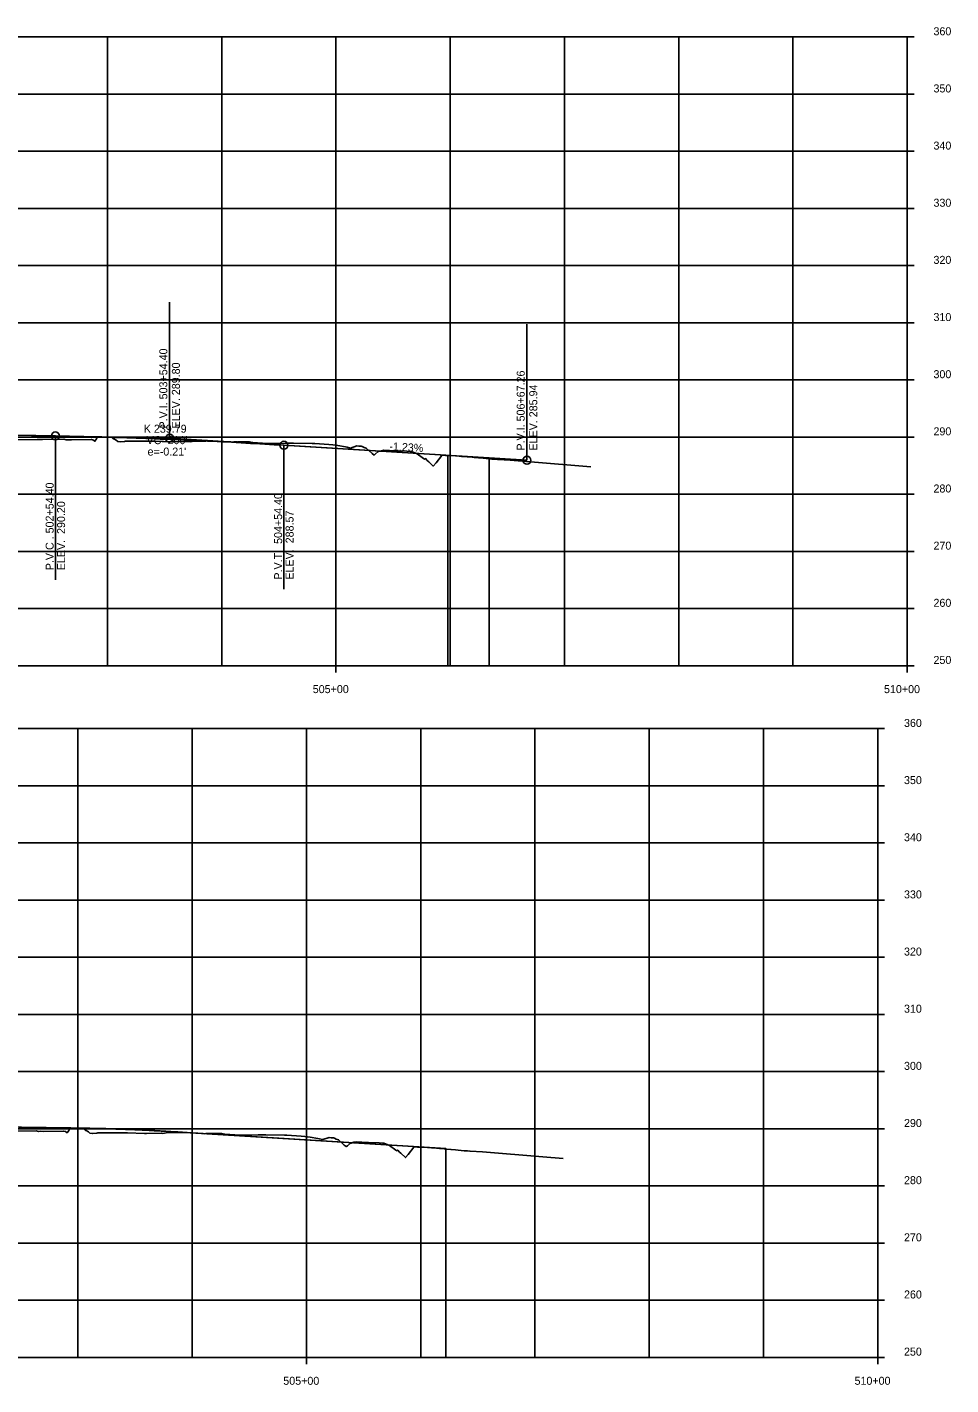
# Model space of a CAD drawing. Extents: x 1300404 to 1323571, y 234004 to 252077.
# Drawn here: x 1319459 to 1320268, y 238049 to 239237 of the extents above; entities that cross this region are included whole.
import ezdxf

# ---------------------------------------------------------------- set-up
doc = ezdxf.new("R2010")
doc.units = 0
for name, color, linetype in [('R_Axis', 7, 'Continuous'), ('R_Axis Annot', 7, 'Continuous'), ('R_Exist Surface', 7, 'Continuous'), ('R_Grid', 7, 'Continuous'), ('R_Temp Barrier Wall', 7, 'Continuous'), ('R_Vert Alg', 7, 'Continuous'), ('R_Vert Alg Annot', 7, 'Continuous')]:
    doc.layers.add(name, color=color, linetype=linetype)

msp = doc.modelspace()

# ---------------------------------------------------------------- linework, layer by layer
at = {"layer": 'R_Axis'}
for p, q in [((1320229.6, 238678), (1320229.6, 239228)), ((1320235.6, 239228), (1320229.6, 239228)), ((1320235.6, 239228), (1320229.6, 239228)), ((1320235.6, 239178), (1320229.6, 239178)), ((1320235.6, 239128), (1320229.6, 239128)), ((1320235.6, 239078), (1320229.6, 239078)), ((1320235.6, 239028), (1320229.6, 239028)), ((1320235.6, 238978), (1320229.6, 238978)), ((1320235.6, 238928), (1320229.6, 238928)), ((1320235.6, 238878), (1320229.6, 238878)), ((1320235.6, 238828), (1320229.6, 238828)), ((1320235.6, 238778), (1320229.6, 238778)), ((1320235.6, 238728), (1320229.6, 238728)), ((1318729.6, 238678), (1320229.6, 238678)), ((1319729.6, 238672), (1319729.6, 238678)), ((1320235.6, 238678), (1320229.6, 238678)), ((1320229.6, 238672), (1320229.6, 238678)), ((1320203.8, 238072.9), (1320203.8, 238622.9)), ((1320209.8, 238622.9), (1320203.8, 238622.9)), ((1320209.8, 238622.9), (1320203.8, 238622.9)), ((1320209.8, 238572.9), (1320203.8, 238572.9)), ((1320209.8, 238522.9), (1320203.8, 238522.9)), ((1320209.8, 238472.9), (1320203.8, 238472.9)), ((1320209.8, 238422.9), (1320203.8, 238422.9)), ((1320209.8, 238372.9), (1320203.8, 238372.9)), ((1320209.8, 238322.9), (1320203.8, 238322.9)), ((1320209.8, 238272.9), (1320203.8, 238272.9)), ((1320209.8, 238222.9), (1320203.8, 238222.9)), ((1320209.8, 238172.9), (1320203.8, 238172.9)), ((1320209.8, 238122.9), (1320203.8, 238122.9)), ((1318703.8, 238072.9), (1320203.8, 238072.9)), ((1319703.8, 238066.9), (1319703.8, 238072.9)), ((1320209.8, 238072.9), (1320203.8, 238072.9)), ((1320203.8, 238066.9), (1320203.8, 238072.9))]:
    msp.add_line(p, q, dxfattribs=at)
at = {"layer": 'R_Exist Surface'}
for points in [[(1319448.9, 238875.7), (1319468.1, 238875.9), (1319470.3, 238875.9), (1319472.8, 238875.9), (1319491.4, 238876.1), (1319493.6, 238875.7), (1319495.6, 238875.7), (1319498.1, 238875.5), (1319515.3, 238875.8), (1319515.4, 238875.8), (1319515.6, 238875.9), (1319517.3, 238875.4), (1319518.6, 238874.4), (1319519.9, 238876.5), (1319521, 238878.2), (1319524.7, 238878.3), (1319533.5, 238877.5), (1319534.6, 238876.4), (1319534.8, 238876.5), (1319535.2, 238876.4), (1319537.3, 238875.3), (1319538.6, 238874), (1319540.8, 238873.7), (1319544.5, 238874.2), (1319545.3, 238874.3), (1319557, 238874.3), (1319557.3, 238874.4), (1319569.1, 238874.4), (1319571.3, 238874.3), (1319586.2, 238873.8), (1319587.1, 238873.8), (1319587.7, 238873.9), (1319588.2, 238873.9), (1319600.9, 238874.2), (1319602.5, 238873.9), (1319605.2, 238874.3), (1319615.7, 238874.5), (1319620.9, 238874.7), (1319636.6, 238873.8), (1319637.5, 238873.7), (1319638.7, 238873.5), (1319640.1, 238873.7), (1319642.9, 238873.7), (1319643.2, 238873.7), (1319643.3, 238873.6), (1319643.4, 238873.6), (1319644, 238873.7), (1319653.9, 238873.8), (1319656.5, 238873.1), (1319656.7, 238873.1), (1319665.4, 238872.6), (1319667.7, 238872.5), (1319685.8, 238872.8), (1319686.4, 238872.8), (1319692.4, 238872.7), (1319708.9, 238872.4), (1319709.4, 238872.4), (1319711, 238872.3), (1319723.4, 238871.4), (1319726.8, 238871.1), (1319729, 238871), (1319731.3, 238870.6), (1319738, 238869.4), (1319739.3, 238869.2), (1319742.4, 238868.4), (1319748, 238870.2), (1319749.7, 238870.1), (1319751.7, 238870.1), (1319752.6, 238869.7), (1319754.2, 238869), (1319756.1, 238868.4), (1319761.2, 238863.7), (1319762.9, 238862.3), (1319764, 238863), (1319766.6, 238865.3), (1319767.1, 238865.4), (1319769.5, 238866.1), (1319771.6, 238866.4), (1319771.6, 238866.4), (1319771.6, 238866.4), (1319781.7, 238866), (1319782.5, 238866), (1319791.6, 238865.7), (1319794.7, 238865.4), (1319795.7, 238865.3), (1319796.3, 238865.1), (1319797.3, 238864.7), (1319800.8, 238863.2), (1319806.3, 238859.2), (1319807, 238858.8), (1319808, 238859.2), (1319809.4, 238857.6), (1319810.8, 238856.4), (1319814.8, 238852.6), (1319817.2, 238855.5), (1319822.2, 238861.9), (1319822.3, 238862), (1319822.4, 238862.1), (1319822.5, 238862.1), (1319825.4, 238862), (1319827.8, 238862), (1319834.1, 238861.6), (1319834.7, 238861.5), (1319837.4, 238861.4), (1319839, 238861.2), (1319839.9, 238861.1), (1319840, 238861.1), (1319841.9, 238860.9), (1319843, 238860.9), (1319844.5, 238860.7), (1319845.5, 238860.6), (1319848.7, 238860.3), (1319850.5, 238860.1), (1319850.7, 238860.1), (1319851, 238860), (1319854.5, 238859.7), (1319854.5, 238859.7), (1319854.7, 238859.7), (1319858.4, 238859.4), (1319858.4, 238859.4), (1319858.5, 238859.4), (1319861, 238859.2), (1319861, 238859.2), (1319866, 238858.8), (1319866, 238858.8), (1319866, 238858.8), (1319869.1, 238858.6), (1319871, 238858.5), (1319871.4, 238858.5), (1319882.1, 238857.7), (1319899.8, 238856.3), (1319917.4, 238854.8), (1319935.1, 238853.4), (1319952.7, 238851.9)], [(1319448.5, 238270.8), (1319467.1, 238271), (1319469.3, 238270.6), (1319471.4, 238270.7), (1319473.8, 238270.5), (1319491, 238270.8), (1319491.1, 238270.8), (1319491.3, 238270.9), (1319493, 238270.4), (1319494.3, 238269.4), (1319495.7, 238271.4), (1319496.7, 238273.1), (1319500.4, 238273.2), (1319509.2, 238272.4), (1319510.3, 238271.4), (1319510.5, 238271.4), (1319510.9, 238271.4), (1319513, 238270.2), (1319514.3, 238269), (1319516.5, 238268.6), (1319520.2, 238269.1), (1319521.1, 238269.3), (1319532.7, 238269.3), (1319533.1, 238269.3), (1319544.9, 238269.3), (1319547, 238269.3), (1319561.9, 238268.7), (1319562.8, 238268.8), (1319563.4, 238268.8), (1319563.9, 238268.8), (1319576.7, 238269.1), (1319578.2, 238268.8), (1319580.9, 238269.2), (1319591.4, 238269.5), (1319596.6, 238269.6), (1319612.3, 238268.8), (1319613.2, 238268.6), (1319614.5, 238268.5), (1319615.8, 238268.6), (1319618.6, 238268.6), (1319619, 238268.6), (1319619, 238268.5), (1319619.1, 238268.6), (1319619.7, 238268.6), (1319629.6, 238268.7), (1319632.2, 238268.1), (1319632.4, 238268), (1319641.1, 238267.5), (1319643.4, 238267.4), (1319661.5, 238267.7), (1319662.1, 238267.7), (1319668.2, 238267.7), (1319684.6, 238267.3), (1319685.1, 238267.3), (1319686.7, 238267.3), (1319699.1, 238266.3), (1319702.5, 238266), (1319704.7, 238265.9), (1319707, 238265.6), (1319713.7, 238264.3), (1319715, 238264.1), (1319718.1, 238263.4), (1319723.7, 238265.1), (1319725.4, 238265), (1319727.4, 238265), (1319728.3, 238264.6), (1319729.9, 238263.9), (1319731.9, 238263.3), (1319736.9, 238258.6), (1319738.6, 238257.3), (1319739.7, 238257.9), (1319742.4, 238260.2), (1319742.8, 238260.4), (1319745.2, 238261), (1319747.3, 238261.4), (1319747.3, 238261.4), (1319747.3, 238261.4), (1319757.4, 238260.9), (1319758.2, 238260.9), (1319767.3, 238260.6), (1319770.4, 238260.3), (1319771.4, 238260.2), (1319772, 238260), (1319773, 238259.6), (1319776.5, 238258.1), (1319782, 238254.2), (1319782.7, 238253.7), (1319783.7, 238254.2), (1319785.1, 238252.5), (1319786.5, 238251.4), (1319790.5, 238247.6), (1319792.9, 238250.4), (1319797.9, 238256.8), (1319798, 238256.9), (1319798.1, 238257), (1319798.2, 238257), (1319801.1, 238256.9), (1319803.5, 238256.9), (1319809.8, 238256.5), (1319810.4, 238256.5), (1319813.1, 238256.3), (1319814.7, 238256.2), (1319815.6, 238256.1), (1319815.7, 238256.1), (1319817.6, 238255.9), (1319818.7, 238255.8), (1319820.2, 238255.6), (1319821.2, 238255.5), (1319824.4, 238255.2), (1319826.2, 238255), (1319826.4, 238255), (1319826.7, 238255), (1319830.2, 238254.6), (1319830.2, 238254.6), (1319830.4, 238254.6), (1319834.1, 238254.3), (1319834.2, 238254.3), (1319834.2, 238254.3), (1319836.7, 238254.1), (1319836.7, 238254.1), (1319841.7, 238253.7), (1319841.7, 238253.7), (1319841.7, 238253.7), (1319844.8, 238253.5), (1319846.7, 238253.4), (1319847.1, 238253.4), (1319857.8, 238252.7), (1319875.5, 238251.2), (1319893.1, 238249.8), (1319910.8, 238248.3), (1319928.4, 238246.8)]]:
    msp.add_lwpolyline(points, dxfattribs=at)
at = {"layer": 'R_Grid'}
for p, q in [((1318729.6, 239228), (1320229.6, 239228)), ((1318729.6, 239228), (1320229.6, 239228)), ((1319529.6, 238678), (1319529.6, 239228)), ((1319629.6, 238678), (1319629.6, 239228)), ((1319729.6, 238678), (1319729.6, 239228)), ((1319829.6, 238678), (1319829.6, 239228)), ((1319929.6, 238678), (1319929.6, 239228)), ((1320029.6, 238678), (1320029.6, 239228)), ((1320129.6, 238678), (1320129.6, 239228)), ((1318729.6, 239178), (1320229.6, 239178)), ((1318729.6, 239128), (1320229.6, 239128)), ((1318729.6, 239078), (1320229.6, 239078)), ((1318729.6, 239028), (1320229.6, 239028)), ((1318729.6, 238978), (1320229.6, 238978)), ((1318729.6, 238928), (1320229.6, 238928)), ((1318729.6, 238878), (1320229.6, 238878)), ((1318729.6, 238828), (1320229.6, 238828)), ((1318729.6, 238778), (1320229.6, 238778)), ((1318729.6, 238728), (1320229.6, 238728)), ((1318703.8, 238622.9), (1320203.8, 238622.9)), ((1318703.8, 238622.9), (1320203.8, 238622.9)), ((1319503.8, 238072.9), (1319503.8, 238622.9)), ((1319603.8, 238072.9), (1319603.8, 238622.9)), ((1319703.8, 238072.9), (1319703.8, 238622.9)), ((1319803.8, 238072.9), (1319803.8, 238622.9)), ((1319903.8, 238072.9), (1319903.8, 238622.9)), ((1320003.8, 238072.9), (1320003.8, 238622.9)), ((1320103.8, 238072.9), (1320103.8, 238622.9)), ((1318703.8, 238572.9), (1320203.8, 238572.9)), ((1318703.8, 238522.9), (1320203.8, 238522.9)), ((1318703.8, 238472.9), (1320203.8, 238472.9)), ((1318703.8, 238422.9), (1320203.8, 238422.9)), ((1318703.8, 238372.9), (1320203.8, 238372.9)), ((1318703.8, 238322.9), (1320203.8, 238322.9)), ((1318703.8, 238272.9), (1320203.8, 238272.9)), ((1318703.8, 238222.9), (1320203.8, 238222.9)), ((1318703.8, 238172.9), (1320203.8, 238172.9)), ((1318703.8, 238122.9), (1320203.8, 238122.9))]:
    msp.add_line(p, q, dxfattribs=at)
at = {"layer": 'R_Temp Barrier Wall'}
for p, q in [((1319584, 238877), (1319213.5, 238884.4)), ((1319896.8, 238857.7), (1319584, 238877)), ((1319827.6, 238678), (1319827.6, 238862)), ((1319863.6, 238678), (1319863.6, 238859)), ((1319203.4, 238278), (1319547.5, 238272.8)), ((1319547.5, 238272.8), (1319825.8, 238255.5)), ((1319803.8, 238072.9), (1319803.8, 238256.9)), ((1319825.8, 238072.9), (1319825.8, 238255.5))]:
    msp.add_line(p, q, dxfattribs=at)
at = {"layer": 'R_Vert Alg'}
for p, q in [((1319584, 238877), (1319584, 238996)), ((1319896.8, 238857.7), (1319896.8, 238976.7)), ((1319263.5, 238883.4), (1319484, 238879)), ((1319484, 238879), (1319484, 238753)), ((1319534, 238878), (1319584, 238877)), ((1319584, 238877), (1319634, 238873.9)), ((1319684, 238870.8), (1319684, 238744.8)), ((1319684, 238870.8), (1319896.8, 238857.7)), ((1319258.4, 238277.2), (1319497.5, 238273.6)), ((1319597.5, 238269.7), (1319825.8, 238255.5))]:
    msp.add_line(p, q, dxfattribs=at)
for points in [[(1319484, 238879), (1319488.1, 238878.9), (1319492.3, 238878.8), (1319496.5, 238878.7), (1319500.6, 238878.6), (1319504.8, 238878.5), (1319509, 238878.4), (1319513.1, 238878.3), (1319517.3, 238878.2), (1319521.5, 238878.1), (1319525.6, 238878), (1319529.8, 238877.9), (1319534, 238877.7), (1319538.1, 238877.6), (1319542.3, 238877.5), (1319546.5, 238877.3), (1319550.6, 238877.2), (1319554.8, 238877.1), (1319559, 238876.9), (1319563.1, 238876.8), (1319567.3, 238876.6), (1319571.5, 238876.5), (1319575.6, 238876.3), (1319579.8, 238876.1), (1319588.1, 238875.8), (1319592.3, 238875.6), (1319596.5, 238875.4), (1319600.6, 238875.3), (1319604.8, 238875.1), (1319609, 238874.9), (1319613.1, 238874.7), (1319617.3, 238874.5), (1319621.5, 238874.3), (1319625.6, 238874.1), (1319629.8, 238873.9), (1319634, 238873.7), (1319638.1, 238873.4), (1319642.3, 238873.2), (1319646.5, 238873), (1319650.6, 238872.8), (1319654.8, 238872.5), (1319659, 238872.3), (1319663.1, 238872.1), (1319667.3, 238871.8), (1319671.5, 238871.6), (1319675.6, 238871.3), (1319679.8, 238871.1), (1319684, 238870.8)], [(1319497.5, 238273.6), (1319499.5, 238273.5), (1319501.6, 238273.5), (1319503.7, 238273.5), (1319505.8, 238273.4), (1319507.9, 238273.4), (1319510, 238273.4), (1319512, 238273.3), (1319514.1, 238273.3), (1319516.2, 238273.2), (1319518.3, 238273.2), (1319520.4, 238273.1), (1319522.5, 238273.1), (1319524.5, 238273), (1319526.6, 238272.9), (1319528.7, 238272.9), (1319530.8, 238272.8), (1319532.9, 238272.8), (1319535, 238272.7), (1319537, 238272.6), (1319539.1, 238272.5), (1319541.2, 238272.5), (1319543.3, 238272.4), (1319545.4, 238272.3), (1319549.5, 238272.2), (1319551.6, 238272.1), (1319553.7, 238272), (1319555.8, 238271.9), (1319557.9, 238271.8), (1319560, 238271.7), (1319562, 238271.6), (1319564.1, 238271.5), (1319566.2, 238271.4), (1319568.3, 238271.3), (1319570.4, 238271.2), (1319572.5, 238271.1), (1319574.5, 238271), (1319576.6, 238270.9), (1319578.7, 238270.8), (1319580.8, 238270.7), (1319582.9, 238270.6), (1319585, 238270.5), (1319587, 238270.3), (1319589.1, 238270.2), (1319591.2, 238270.1), (1319593.3, 238270), (1319595.4, 238269.8), (1319597.5, 238269.7)]]:
    msp.add_lwpolyline(points, dxfattribs=at)
for centre in [(1319484, 238879), (1319584, 238877), (1319684, 238870.8), (1319896.8, 238857.7)]:
    msp.add_circle(centre, 3.5, dxfattribs=at)

# ---------------------------------------------------------------- texts
at = {"layer": 'R_Axis Annot'}
for s, p in [('360', (1320252.6, 239229.5)), ('360', (1320252.6, 239229.5)), ('350', (1320252.6, 239179.5)), ('340', (1320252.6, 239129.5)), ('330', (1320252.6, 239079.5)), ('320', (1320252.6, 239029.5)), ('310', (1320252.6, 238979.5)), ('300', (1320252.6, 238929.5)), ('290', (1320252.6, 238879.5)), ('280', (1320252.6, 238829.5)), ('270', (1320252.6, 238779.5)), ('260', (1320252.6, 238729.5)), ('250', (1320252.6, 238679.5)), ('505+00', (1319709.3, 238654)), ('510+00', (1320209.3, 238654)), ('360', (1320226.8, 238624.4)), ('360', (1320226.8, 238624.4)), ('350', (1320226.8, 238574.4)), ('340', (1320226.8, 238524.4)), ('330', (1320226.8, 238474.4)), ('320', (1320226.8, 238424.4)), ('310', (1320226.8, 238374.4)), ('300', (1320226.8, 238324.4)), ('290', (1320226.8, 238274.4)), ('280', (1320226.8, 238224.4)), ('270', (1320226.8, 238174.4)), ('260', (1320226.8, 238124.4)), ('250', (1320226.8, 238074.4)), ('505+00', (1319683.5, 238048.9)), ('510+00', (1320183.5, 238048.9))]:
    msp.add_text(s, height=7, dxfattribs=at).set_placement(p)
at = {"layer": 'R_Vert Alg Annot'}
for s, rotation, p in [('P.V.I. 503+54.40', 90, (1319582, 238885.5)), ('ELEV. 289.80', 90, (1319593, 238885.5)), ('P.V.I. 506+67.26', 90, (1319894.8, 238866.2)), ('ELEV. 285.94', 90, (1319905.8, 238866.2)), ('-1.23%', 356.4692, (1319776.2, 238866.6)), ('P.V.C . 502+54.40', 90, (1319482.5, 238761.5)), ('P.V.T.  504+54.40', 90, (1319682.5, 238753.3)), ('ELEV.  290.20', 90, (1319492.5, 238761.5)), ('ELEV.  288.57', 90, (1319692.5, 238753.3))]:
    msp.add_text(s, height=7, rotation=rotation, dxfattribs=at).set_placement(p)
for s, p in [('K 239.79', (1319561.4, 238881.8)), ("VC=200'", (1319563.8, 238871.8)), ("e=-0.21'", (1319564.7, 238861.8))]:
    msp.add_text(s, height=7, dxfattribs=at).set_placement(p)

doc.saveas('drawing.dxf')
